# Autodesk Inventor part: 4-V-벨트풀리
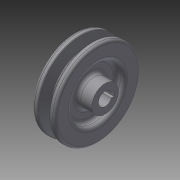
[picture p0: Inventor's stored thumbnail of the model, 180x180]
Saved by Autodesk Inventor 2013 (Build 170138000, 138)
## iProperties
Created: 2015-02
Part Number: 4-V-벨트풀리
Material: 일반
Document SubType Name: Modeling
Designer: Administrator
Density: 1 g/cm^3
Author: Administrator
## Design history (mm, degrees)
sketch "스케치1"
  geometry: L1 (0, 0)-(25, 0); L2 (0, 5.5)-(25, 5.5); L3 (25, 5.5)-(25, 11); L4 (25, 11)-(13, 11); L5 (13, 11)-(13, 21.5); L6 (13, 21.5)-(19, 21.5); L7 (19, 21.5)-(19, 35.2); L8 (19, 35.2)-(14.325, 35.2); L9 (14.325, 35.2)-(11.574, 26.2); L10 (11.574, 26.2)-(7.426, 26.2); L11 (7.426, 26.2)-(4.675, 35.2); L12 (4.675, 35.2)-(0, 35.2); L13 (0, 35.2)-(0, 21.5); L14 (0, 21.5)-(6, 21.5); L15 (6, 21.5)-(6, 11); L16 (6, 11)-(0, 11); L17 (0, 11)-(0, 5.5); 2 further points
  constraints: 34 end point, 12 parallel, 4 horizontal alignment, 3 equal length, 3 vertical alignment, 2 perpendicular, 2 point on line, 1 horizontal
  dimensions: "d0" = 25 distance of L1.start L1.end; "d1" = 11 diameter of L2 L1; "d2" = 22 diameter of L4 L1; "d3" = 43 diameter of L14 L1; "d4" = 19 distance between parallel lines of L7 L13; "d5" = 6 distance between parallel lines of L7 L5; "d6" = 2.7 distance from line of L12 point (5.5, 32.5); "d7" = 6.3 distance from line of L10 point (5.5, 32.5); "d8" = 8 distance of point (13.5, 32.5) point (5.5, 32.5); "d9" = 34 deg angle of L9 L11; "d10" = 65 diameter of point (5.5, 32.5) L1
revolve "회전1" sketch "스케치1" stored, may be unused: angle "d11" = 90 deg
sketch "스케치2"
  geometry: L1 (-2, 5.123)-(-2, 7.3); L2 (-2, 7.3)-(2, 7.3); L3 (2, 7.3)-(2, 5.123); A1 r 5.5 centre (0, 0) between (-2, 5.123) and (2, 5.123) reference; 1 further point
  constraints: 6 end point, 2 point on circle, 1 midpoint, 1 parallel, 1 perpendicular, 1 vertical, 1 vertical alignment
  dimensions: "d12" = 4 distance between parallel lines of L1 L3; "d14" = 12.8 dimension on A1 L2
extrude "돌출1" cut sketch "스케치2" stored distance "d15" = 10; taper "d16" = 0 deg
fillet "모깎기1" dims "d17" = 2, "d18" = 0.5, "d19" = 1
fillet "모깎기2" dims "d20" = 3
fillet "모깎기3" dims "d21" = 3
node "솔리드1"
